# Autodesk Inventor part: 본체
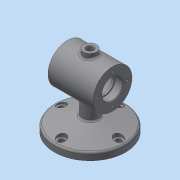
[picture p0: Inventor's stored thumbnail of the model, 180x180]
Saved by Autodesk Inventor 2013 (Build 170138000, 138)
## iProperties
Created: 2018-12
Part Number: 본체
Material: 일반
Document SubType Name: Modeling
Designer: dgall
Density: 1 g/cm^3
Author: dgall
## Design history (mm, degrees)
sketch "스케치1"
  geometry: C1 r 55 at (0, 0); 1 further point
  constraints: 1 centre point, 1 coincident
  dimensions: "d3" = 110 diameter of C1
extrude "돌출1" new body sketch "스케치1" distance "d0" = 11; taper "d1" = 0 deg
sketch "스케치3"
  geometry: C1 r 30 at (0, 75); 1 further point
  constraints: 1 centre point, 1 vertical alignment
  dimensions: "d6" = 75 distance of point (0, 0) C1.centre; "d7" = 60 diameter of C1
extrude "돌출2" join sketch "스케치3" stored distance "d8" = 70; taper "d9" = 0 deg
sketch "스케치4"
  geometry: C1 r 30 at (0, 0) reference; C2 r 14 at (0, 0); 1 further point
  constraints: 1 centre point, 1 coincident
  dimensions: "d10" = 28 diameter of C2
extrude "돌출3" cut sketch "스케치4" distance "d12" = 70; taper "d13" = 0 deg
node "작업 평면1"
sketch "스케치5"
  geometry: C1 r 14 at (0, 0) reference; C2 r 25 at (0, 0); 1 further point
  constraints: 1 centre point, 1 coincident
  dimensions: "d15" = 50 diameter of C2
extrude "돌출4" cut sketch "스케치5" stored distance "d17" = 40; taper "d18" = 0 deg
hole "구멍1" diameter "d21" = 32; stored, may be unused: countersink angle "d25" = 90 deg, drill point angle "d27" = 0 deg; dims "d19" = 10, "d20" = 10, "d22" = 6, "d23" = 4, "d24" = 2, "d26" = 12
hole "구멍2" diameter "d30" = 32; stored, may be unused: countersink angle "d34" = 90 deg, drill point angle "d36" = 0 deg; dims "d28" = 10, "d29" = 10, "d31" = 6, "d32" = 4, "d33" = 2, "d35" = 12
sketch "스케치6"
  geometry: C1 r 55 at (0, 0) reference; C2 r 12 at (0, 0)
  constraints: 1 centre point, 1 coincident
  dimensions: "d37" = 24 diameter of C2
extrude "돌출5" join sketch "스케치6" stored distance "d39" = 40; taper "d40" = 0 deg
sketch "스케치7"
  geometry: L1 (55, 11)-(-55, 11) reference; L2 (-55, 0)-(55, 0) reference; L3 (55, 0)-(55, 11) reference; L4 (12, 11)-(12, 45) reference; L5 (12, 11)-(12, 45) reference; L6 (55, 11)-(-55, 11) reference; L7 (55, 11)-(5, 24.397); L8 (0, 0)-(0, 105); L9 (35, 105)-(-35, 105) reference; L10 (5, 24.397)-(5, 11); L11 (55, 11)-(5, 11)
  constraints: 8 end point, 2 perpendicular, 1 midpoint, 1 point on line
  dimensions: "d42" = 75 deg angle of L7 L3; "d43" = 50 horizontal distance of L3.end L7.end
revolve "회전1" sketch "스케치7" stored, may be unused: angle "d44" = 90 deg
sketch "스케치8"
  geometry: C1 r 55 at (0, 0) reference; 4 further points
  constraints: 2 horizontal alignment, 2 vertical alignment
  dimensions: "d47" = 88 distance of point (44, 0) point (-44, 0); "d49" = 88 distance of point (0, 44) point (0, -44); "d50" = 44 distance of C1.centre point (-44, 0); "d51" = 44 distance of point (0, -44) C1.centre
hole "구멍3" sketch "스케치8" at (0, 44), (-44, 0), (0, -44), (44, 0) diameter "d52" = 9; stored, may be unused: countersink angle "d56" = 90 deg, drill point angle "d58" = 0 deg; dims "d53" = 6, "d54" = 4, "d55" = 2, "d57" = 30
node "작업 평면3"
sketch "스케치9"
  geometry: C1 r 4.5 at (0, 44) reference; C2 r 4.5 at (-44, 0) reference; C3 r 4.5 at (0, -44) reference; C4 r 4.5 at (44, 0) reference; C5 r 7 at (0, 44); C6 r 7 at (-44, 0); C7 r 7 at (44, 0); C8 r 7 at (0, -44); 1 further point
  constraints: 4 centre point, 4 coincident, 3 equal radius
  dimensions: "d61" = 14 diameter of C5
extrude "돌출6" cut sketch "스케치9" distance "d63" = 15; taper "d64" = 0 deg
sketch "스케치10"
  geometry: C1 r 16 at (0, 0) reference; 5 further points
  constraints: 2 horizontal alignment, 2 vertical alignment
  dimensions: "d65" = 46 distance of point (23, 0) point (-23, 0); "d67" = 46 distance of point (0, 23) point (0, -23); "d68" = 23 distance of C1.centre point (0, 23); "d69" = 23 distance of C1.centre point (-23, 0)
hole "구멍4" sketch "스케치10" at (0, 23), (-23, 0), (0, -23), (23, 0) diameter "d70" = 3.242; stored, may be unused: countersink angle "d74" = 90 deg, drill point angle "d76" = 118 deg; dims "d71" = 8, "d72" = 4, "d73" = 2, "d75" = 10
node "작업 평면4"
sketch "스케치11"
  geometry: C1 r 10 at (0, 0); C2 r 5 at (0, 0); 1 further point
  constraints: 2 centre point, 2 coincident
  dimensions: "d78" = 20 diameter of C1; "d79" = 10 diameter of C2
extrude "돌출7" join sketch "스케치11" stored distance "d80" = 15; taper "d81" = 0 deg
chamfer "모따기1" distance "d82" = 1; stored, may be unused: second distance "d83" = 2, angle "d84" = 45 deg
fillet "모깎기1" dims "d85" = 3
node "작업 평면6"
sketch "스케치13"
  geometry: L1 (-35, 105)-(-35, 45) reference; 2 further points
  constraints: 1 other
  dimensions: "d90" = 35 distance from line of L1 point (0, 75); "d92" = 30 vertical distance of L1.start point (0, 75)
feature "엠보싱1" sketch "스케치13" dims "d17" = 40, "d18" = 0, "d93" = 0.5, "d94" = 0
extrude "돌출8" cut sketch "스케치11" distance "d95" = 15; taper "d96" = 0 deg
fillet "모깎기2" dims "d99" = 0.3
node "솔리드1"
mirror "대칭1"
node "투영된 루프1"
other parameters: "d14" = -35, "d60" = -25, "d77" = -112
